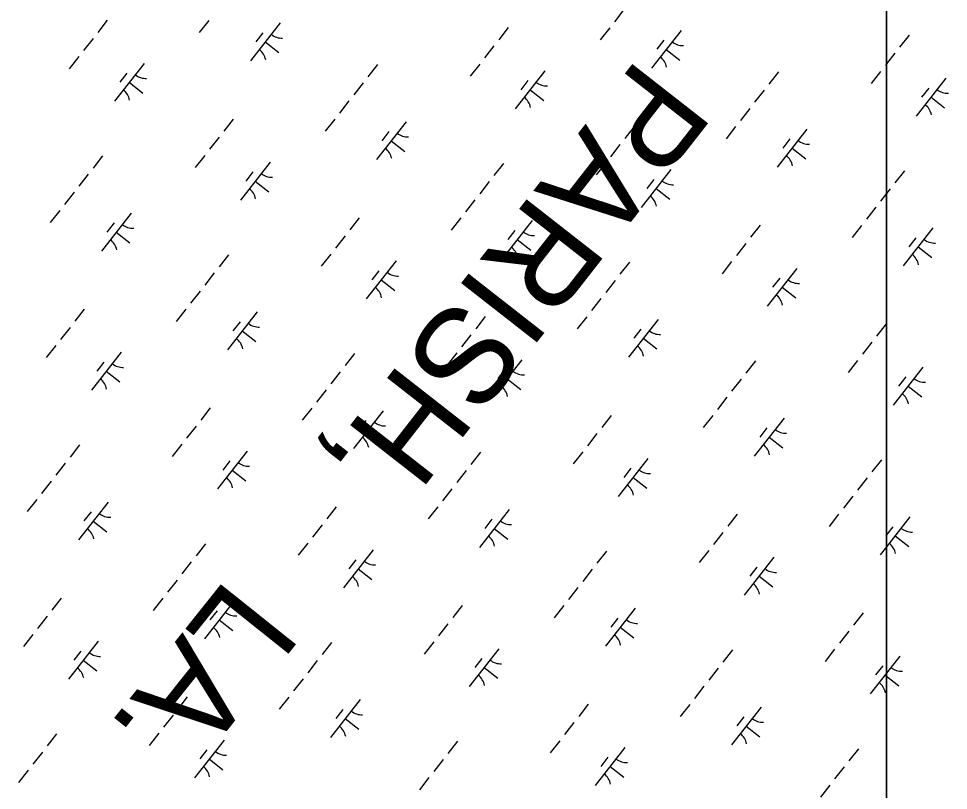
# Model space of a CAD drawing. Extents: x 3896831 to 3918110, y 171006 to 193349.
# Drawn here: x 3905077 to 3906044, y 182282 to 183084 of the extents above; entities that cross this region are included whole.
import ezdxf

# ---------------------------------------------------------------- set-up
doc = ezdxf.new("R2010")
doc.units = 0
doc.layers.add('V-TOPO-GNAM-IDEN', color=7, linetype='Continuous')
doc.layers.add('V-WETL-SWMP', color=7, linetype='Continuous')

msp = doc.modelspace()

# ---------------------------------------------------------------- linework, layer by layer
at = {"layer": 'V-WETL-SWMP'}
for p, q in [((3905979.34, 184854.89), (3905979.34, 179465.22)), ((3905979.34, 179465.22), (3905979.34, 184854.89)), ((3905706.44, 183092.9), (3905696.57, 183080.31)), ((3905169.53, 183081.84), (3905159.66, 183069.25)), ((3905275, 183081.71), (3905265.13, 183069.12)), ((3905349.13, 183078.97), (3905318.29, 183039.62)), ((3905331.34, 183068.78), (3905323.94, 183059.33)), ((3905586.18, 183074.14), (3905576.31, 183061.55)), ((3905691.64, 183074.01), (3905681.77, 183061.42)), ((3905765.77, 183071.27), (3905734.93, 183031.92)), ((3906002.82, 183066.44), (3905992.95, 183053.85)), ((3905154.73, 183062.95), (3905144.86, 183050.36)), ((3905333.71, 183059.3), (3905347.88, 183048.19)), ((3905747.98, 183061.08), (3905740.58, 183051.63)), ((3905571.37, 183055.25), (3905561.5, 183042.66)), ((3905750.35, 183051.6), (3905764.52, 183040.49)), ((3905988.01, 183047.55), (3905979.34, 183036.48)), ((3905139.92, 183044.06), (3905130.05, 183031.47)), ((3905207.74, 183037.02), (3905176.9, 182997.67)), ((3905450.33, 183035.77), (3905440.46, 183023.18)), ((3905556.57, 183036.36), (3905546.7, 183023.77)), ((3905624.38, 183029.32), (3905593.54, 182989.97)), ((3905866.97, 183028.07), (3905857.1, 183015.48)), ((3905973.21, 183028.66), (3905963.34, 183016.07)), ((3905979.34, 183036.48), (3905978.14, 183034.96)), ((3905189.95, 183026.83), (3905182.54, 183017.39)), ((3905606.59, 183019.13), (3905599.19, 183009.69)), ((3906041.03, 183021.62), (3906010.18, 182982.27)), ((3905192.32, 183017.35), (3905206.49, 183006.24)), ((3905435.53, 183016.88), (3905425.66, 183004.29)), ((3905608.96, 183009.65), (3905623.13, 182998.54)), ((3905852.17, 183009.18), (3905842.3, 182996.59)), ((3906023.23, 183011.43), (3906015.83, 183001.99)), ((3906025.6, 183001.95), (3906039.77, 182990.84)), ((3905420.72, 182997.99), (3905410.85, 182985.4)), ((3905837.36, 182990.29), (3905827.49, 182977.7)), ((3905300.45, 182979.23), (3905290.58, 182966.64)), ((3905405.92, 182979.1), (3905396.05, 182966.51)), ((3905480.05, 182976.37), (3905449.21, 182937.01)), ((3905717.1, 182971.53), (3905707.23, 182958.94)), ((3905822.56, 182971.4), (3905812.69, 182958.81)), ((3905285.65, 182960.34), (3905275.78, 182947.75)), ((3905462.26, 182966.17), (3905454.85, 182956.73)), ((3905896.69, 182968.67), (3905865.85, 182929.31)), ((3905464.63, 182956.69), (3905478.79, 182945.58)), ((3905702.29, 182952.64), (3905692.42, 182940.05)), ((3905878.9, 182958.47), (3905871.5, 182949.03)), ((3905164.61, 182940.86), (3905154.74, 182928.27)), ((3905270.84, 182941.45), (3905260.97, 182928.86)), ((3905881.27, 182948.99), (3905895.44, 182937.88)), ((3905338.66, 182934.42), (3905307.82, 182895.06)), ((3905581.25, 182933.16), (3905571.38, 182920.57)), ((3905687.49, 182933.75), (3905677.62, 182921.16)), ((3905149.8, 182921.97), (3905139.93, 182909.38)), ((3905320.87, 182924.22), (3905313.46, 182914.78)), ((3905755.3, 182926.72), (3905724.46, 182887.36)), ((3905997.89, 182925.46), (3905988.02, 182912.87)), ((3905323.24, 182914.74), (3905337.4, 182903.64)), ((3905566.44, 182914.27), (3905556.57, 182901.68)), ((3905737.51, 182916.52), (3905730.11, 182907.08)), ((3905135, 182903.08), (3905125.13, 182890.49)), ((3905739.88, 182907.04), (3905754.05, 182895.94)), ((3905983.09, 182906.57), (3905979.34, 182901.79)), ((3905551.64, 182895.38), (3905541.77, 182882.79)), ((3905979.34, 182901.79), (3905973.22, 182893.98)), ((3905120.19, 182884.19), (3905110.32, 182871.6)), ((3905968.28, 182887.68), (3905958.41, 182875.09)), ((3905194.32, 182881.46), (3905163.48, 182842.1)), ((3905431.37, 182876.62), (3905421.5, 182864.03)), ((3905536.83, 182876.49), (3905526.96, 182863.9)), ((3905610.97, 182873.76), (3905580.12, 182834.4)), ((3905176.53, 182871.26), (3905169.13, 182861.82)), ((3905593.17, 182863.56), (3905585.77, 182854.12)), ((3905848.01, 182868.92), (3905838.14, 182856.33)), ((3905953.48, 182868.79), (3905943.61, 182856.2)), ((3906027.61, 182866.06), (3905996.77, 182826.7)), ((3905178.9, 182861.78), (3905193.07, 182850.68)), ((3905416.57, 182857.73), (3905406.7, 182845.14)), ((3905595.55, 182854.08), (3905609.71, 182842.98)), ((3906009.82, 182855.86), (3906002.41, 182846.42)), ((3905833.21, 182850.03), (3905823.34, 182837.44)), ((3906012.19, 182846.38), (3906026.36, 182835.28)), ((3905295.52, 182838.25), (3905285.65, 182825.66)), ((3905401.76, 182838.84), (3905391.89, 182826.25)), ((3905469.58, 182831.81), (3905438.73, 182792.45)), ((3905712.17, 182830.55), (3905702.3, 182817.96)), ((3905818.4, 182831.14), (3905808.53, 182818.55)), ((3905280.72, 182819.36), (3905270.85, 182806.77)), ((3905451.78, 182821.61), (3905444.38, 182812.17)), ((3905886.22, 182824.11), (3905855.38, 182784.75)), ((3905454.16, 182812.13), (3905468.32, 182801.03)), ((3905697.36, 182811.66), (3905687.49, 182799.07)), ((3905868.43, 182813.91), (3905861.02, 182804.47)), ((3905265.91, 182800.47), (3905256.04, 182787.88)), ((3905870.8, 182804.43), (3905884.97, 182793.33)), ((3905682.56, 182792.77), (3905672.69, 182780.18)), ((3905145.65, 182781.71), (3905135.78, 182769.12)), ((3905251.11, 182781.58), (3905241.24, 182768.99)), ((3905325.24, 182778.85), (3905294.4, 182739.49)), ((3905307.45, 182768.65), (3905300.05, 182759.21)), ((3905562.29, 182774.01), (3905552.42, 182761.42)), ((3905667.75, 182773.88), (3905657.88, 182761.29)), ((3905741.89, 182771.15), (3905711.04, 182731.79)), ((3905130.84, 182762.82), (3905120.97, 182750.23)), ((3905309.82, 182759.17), (3905323.99, 182748.07)), ((3905724.09, 182760.95), (3905716.69, 182751.51)), ((3905978.93, 182766.31), (3905969.06, 182753.72)), ((3905547.48, 182755.12), (3905537.61, 182742.53)), ((3905726.46, 182751.47), (3905740.63, 182740.37)), ((3905116.04, 182743.93), (3905106.17, 182731.34)), ((3905964.13, 182747.42), (3905954.26, 182734.83)), ((3905183.85, 182736.9), (3905153.01, 182697.55)), ((3905426.44, 182735.64), (3905416.57, 182723.05)), ((3905532.68, 182736.23), (3905522.81, 182723.64)), ((3905600.5, 182729.2), (3905569.65, 182689.85)), ((3905949.32, 182728.54), (3905939.45, 182715.94)), ((3905166.06, 182726.7), (3905158.66, 182717.26)), ((3905582.7, 182719), (3905575.3, 182709.56)), ((3905843.09, 182727.94), (3905833.22, 182715.35)), ((3906017.14, 182721.5), (3905986.3, 182682.15)), ((3905168.43, 182717.22), (3905182.6, 182706.12)), ((3905411.64, 182716.75), (3905401.77, 182704.16)), ((3905585.07, 182709.52), (3905599.24, 182698.42)), ((3905828.28, 182709.05), (3905818.41, 182696.46)), ((3905999.35, 182711.3), (3905991.94, 182701.86)), ((3906001.72, 182701.82), (3906015.88, 182690.72)), ((3905396.83, 182697.86), (3905386.96, 182685.27)), ((3905813.48, 182690.16), (3905803.61, 182677.57)), ((3905276.56, 182679.11), (3905266.69, 182666.51)), ((3905382.03, 182678.97), (3905372.16, 182666.38)), ((3905456.16, 182676.24), (3905425.32, 182636.89)), ((3905693.21, 182671.41), (3905683.34, 182658.81)), ((3905798.67, 182671.27), (3905788.8, 182658.68)), ((3905438.37, 182666.04), (3905430.97, 182656.6)), ((3905872.8, 182668.54), (3905841.96, 182629.19)), ((3905261.76, 182660.22), (3905251.89, 182647.62)), ((3905440.74, 182656.56), (3905454.91, 182645.46)), ((3905678.4, 182652.52), (3905668.53, 182639.92)), ((3905855.01, 182658.34), (3905847.61, 182648.9)), ((3905246.96, 182641.33), (3905237.09, 182628.73)), ((3905857.38, 182648.86), (3905871.55, 182637.76)), ((3905140.72, 182640.73), (3905130.85, 182628.14)), ((3905314.77, 182634.29), (3905283.93, 182594.94)), ((3905557.36, 182633.03), (3905547.49, 182620.44)), ((3905663.6, 182633.63), (3905653.73, 182621.03)), ((3905125.91, 182621.85), (3905116.04, 182609.25)), ((3905296.98, 182624.1), (3905289.58, 182614.65)), ((3905731.41, 182626.59), (3905700.57, 182587.24)), ((3905974, 182625.33), (3905964.13, 182612.74)), ((3905299.35, 182614.61), (3905313.52, 182603.51)), ((3905542.56, 182614.15), (3905532.69, 182601.55)), ((3905713.62, 182616.4), (3905706.22, 182606.95)), ((3905111.11, 182602.96), (3905101.24, 182590.36)), ((3905715.99, 182606.91), (3905730.16, 182595.81)), ((3905959.2, 182606.45), (3905949.33, 182593.85)), ((3905527.75, 182595.26), (3905517.88, 182582.66)), ((3905096.3, 182584.07), (3905086.43, 182571.47)), ((3905944.39, 182587.56), (3905934.52, 182574.96)), ((3905170.44, 182581.33), (3905139.59, 182541.98)), ((3905407.48, 182576.5), (3905397.61, 182563.9)), ((3905512.95, 182576.37), (3905503.08, 182563.77)), ((3905587.08, 182573.63), (3905556.24, 182534.28)), ((3905152.64, 182571.14), (3905145.24, 182561.69)), ((3905824.13, 182568.8), (3905814.26, 182556.2)), ((3905929.59, 182568.67), (3905919.72, 182556.07)), ((3906003.72, 182565.93), (3905979.34, 182534.82)), ((3905155.02, 182561.65), (3905169.18, 182550.55)), ((3905392.68, 182557.61), (3905382.81, 182545.01)), ((3905569.29, 182563.44), (3905561.88, 182553.99)), ((3905985.93, 182555.74), (3905979.34, 182547.33)), ((3905571.66, 182553.95), (3905585.83, 182542.85)), ((3905809.32, 182549.91), (3905799.45, 182537.31)), ((3905979.34, 182547.33), (3905978.53, 182546.29)), ((3905988.3, 182546.25), (3906002.47, 182535.15)), ((3905271.64, 182538.13), (3905261.77, 182525.53)), ((3905377.87, 182538.72), (3905368, 182526.12)), ((3905445.69, 182531.68), (3905414.85, 182492.33)), ((3905688.28, 182530.43), (3905678.41, 182517.83)), ((3905794.52, 182531.02), (3905784.65, 182518.42)), ((3905979.34, 182534.82), (3905972.88, 182526.58)), ((3905256.83, 182519.24), (3905246.96, 182506.64)), ((3905427.9, 182521.49), (3905420.49, 182512.04)), ((3905862.33, 182523.98), (3905831.49, 182484.63)), ((3905430.27, 182512.01), (3905444.44, 182500.9)), ((3905673.47, 182511.54), (3905663.6, 182498.94)), ((3905844.54, 182513.79), (3905837.14, 182504.34)), ((3905242.03, 182500.35), (3905232.16, 182487.75)), ((3905846.91, 182504.31), (3905861.08, 182493.2)), ((3905658.67, 182492.65), (3905648.8, 182480.05)), ((3905121.76, 182481.59), (3905111.89, 182469)), ((3905227.22, 182481.46), (3905217.35, 182468.86)), ((3905301.36, 182478.72), (3905270.51, 182439.37)), ((3905283.56, 182468.53), (3905276.16, 182459.08)), ((3905538.4, 182473.89), (3905528.53, 182461.3)), ((3905643.86, 182473.76), (3905633.99, 182461.16)), ((3905718, 182471.02), (3905687.16, 182431.67)), ((3905106.95, 182462.7), (3905097.08, 182450.11)), ((3905285.93, 182459.05), (3905300.1, 182447.94)), ((3905700.21, 182460.83), (3905692.8, 182451.38)), ((3905955.04, 182466.19), (3905945.17, 182453.6)), ((3905523.6, 182455), (3905513.73, 182442.41)), ((3905702.58, 182451.35), (3905716.74, 182440.24)), ((3905092.15, 182443.81), (3905082.28, 182431.22)), ((3905940.24, 182447.3), (3905930.37, 182434.71)), ((3905159.97, 182436.77), (3905129.12, 182397.42)), ((3905402.56, 182435.52), (3905392.69, 182422.92)), ((3905508.79, 182436.11), (3905498.92, 182423.52)), ((3905576.61, 182429.07), (3905545.76, 182389.72)), ((3905142.17, 182426.58), (3905134.77, 182417.13)), ((3905819.2, 182427.82), (3905809.33, 182415.22)), ((3905925.43, 182428.41), (3905915.57, 182415.82)), ((3905993.25, 182421.37), (3905979.34, 182403.62)), ((3905144.54, 182417.1), (3905158.71, 182405.99)), ((3905387.75, 182416.63), (3905377.88, 182404.03)), ((3905558.82, 182418.88), (3905551.41, 182409.43)), ((3905561.19, 182409.4), (3905575.35, 182398.29)), ((3905975.46, 182411.18), (3905968.06, 182401.73)), ((3905804.39, 182408.93), (3905794.52, 182396.34)), ((3905979.34, 182403.62), (3905962.41, 182382.02)), ((3905977.83, 182401.7), (3905979.34, 182400.51)), ((3905979.34, 182400.51), (3905992, 182390.59)), ((3905372.95, 182397.74), (3905363.08, 182385.15)), ((3905789.59, 182390.04), (3905779.72, 182377.45)), ((3905252.68, 182378.98), (3905242.81, 182366.39)), ((3905358.14, 182378.85), (3905348.27, 182366.26)), ((3905432.27, 182376.11), (3905401.43, 182336.76)), ((3905669.32, 182371.28), (3905659.45, 182358.69)), ((3905774.78, 182371.15), (3905764.91, 182358.56)), ((3905414.48, 182365.92), (3905407.08, 182356.47)), ((3905848.92, 182368.41), (3905818.07, 182329.06)), ((3905237.87, 182360.09), (3905228, 182347.5)), ((3905416.85, 182356.44), (3905431.02, 182345.33)), ((3905654.52, 182352.39), (3905644.65, 182339.8)), ((3905831.12, 182358.22), (3905823.72, 182348.77)), ((3905833.5, 182348.74), (3905847.66, 182337.63)), ((3905116.83, 182340.61), (3905106.96, 182328.02)), ((3905223.07, 182341.2), (3905213.2, 182328.61)), ((3905290.88, 182334.16), (3905260.04, 182294.81)), ((3905533.47, 182332.91), (3905523.6, 182320.32)), ((3905639.71, 182333.5), (3905629.84, 182320.91)), ((3905273.09, 182323.97), (3905265.69, 182314.53)), ((3905707.53, 182326.46), (3905676.68, 182287.11)), ((3905950.12, 182325.21), (3905940.25, 182312.62)), ((3905102.03, 182321.72), (3905092.16, 182309.13)), ((3905275.46, 182314.49), (3905289.63, 182303.38)), ((3905518.67, 182314.02), (3905508.8, 182301.43)), ((3905689.73, 182316.27), (3905682.33, 182306.83)), ((3905692.11, 182306.79), (3905706.27, 182295.68)), ((3905935.31, 182306.32), (3905925.44, 182293.73)), ((3905087.22, 182302.83), (3905077.35, 182290.24)), ((3905503.86, 182295.13), (3905493.99, 182282.54)), ((3905920.51, 182287.43), (3905910.64, 182274.84))]:
    msp.add_line(p, q, dxfattribs=at)
for centre, start, end in [((3905350.93, 183080.89), 231.14028, 272.68394), ((3905767.58, 183073.19), 231.14028, 272.68394), ((3905316.86, 183037.41), 11.14028, 52.68394), ((3905733.5, 183029.71), 11.14028, 52.68394), ((3905209.54, 183038.94), 231.14028, 272.68394), ((3905175.47, 182995.46), 11.14028, 52.68394), ((3905626.19, 183031.24), 231.14028, 272.68394), ((3906042.83, 183023.54), 231.14028, 272.68394), ((3905592.11, 182987.76), 11.14028, 52.68394), ((3906008.75, 182980.06), 11.14028, 52.68394), ((3905481.85, 182978.28), 231.14028, 272.68394), ((3905898.5, 182970.58), 231.14028, 272.68394), ((3905447.78, 182934.8), 11.14028, 52.68394), ((3905864.42, 182927.1), 11.14028, 52.68394), ((3905340.46, 182936.33), 231.14028, 272.68394), ((3905757.11, 182928.63), 231.14028, 272.68394), ((3905306.39, 182892.85), 11.14028, 52.68394), ((3905723.03, 182885.15), 11.14028, 52.68394), ((3905196.13, 182883.37), 231.14028, 272.68394), ((3905162.05, 182839.89), 11.14028, 52.68394), ((3905612.77, 182875.67), 231.14028, 272.68394), ((3906029.41, 182867.97), 231.14028, 272.68394), ((3905578.69, 182832.19), 11.14028, 52.68394), ((3905995.34, 182824.49), 11.14028, 52.68394), ((3905471.38, 182833.72), 231.14028, 272.68394), ((3905888.02, 182826.02), 231.14028, 272.68394), ((3905437.3, 182790.24), 11.14028, 52.68394), ((3905853.95, 182782.54), 11.14028, 52.68394), ((3905327.05, 182780.76), 231.14028, 272.68394), ((3905743.69, 182773.06), 231.14028, 272.68394), ((3905292.97, 182737.28), 11.14028, 52.68394), ((3905709.61, 182729.58), 11.14028, 52.68394), ((3905185.66, 182738.82), 231.14028, 272.68394), ((3905151.58, 182695.34), 11.14028, 52.68394), ((3905602.3, 182731.12), 231.14028, 272.68394), ((3906018.94, 182723.42), 231.14028, 272.68394), ((3905568.22, 182687.64), 11.14028, 52.68394), ((3905984.86, 182679.94), 11.14028, 52.68394), ((3905457.97, 182678.16), 231.14028, 272.68394), ((3905874.61, 182670.46), 231.14028, 272.68394), ((3905423.89, 182634.68), 11.14028, 52.68394), ((3905840.53, 182626.98), 11.14028, 52.68394), ((3905316.58, 182636.21), 231.14028, 272.68394), ((3905733.22, 182628.51), 231.14028, 272.68394), ((3905282.5, 182592.73), 11.14028, 52.68394), ((3905699.14, 182585.03), 11.14028, 52.68394), ((3905172.24, 182583.25), 231.14028, 272.68394), ((3905588.88, 182575.55), 231.14028, 272.68394), ((3905138.16, 182539.77), 11.14028, 52.68394), ((3905554.81, 182532.07), 11.14028, 52.68394), ((3906005.53, 182567.85), 231.14028, 272.68394), ((3905971.45, 182524.37), 11.14028, 52.68394), ((3905447.49, 182533.6), 231.14028, 272.68394), ((3905864.14, 182525.9), 231.14028, 272.68394), ((3905413.42, 182490.12), 11.14028, 52.68394), ((3905830.06, 182482.42), 11.14028, 52.68394), ((3905303.16, 182480.64), 231.14028, 272.68394), ((3905719.8, 182472.94), 231.14028, 272.68394), ((3905269.08, 182437.16), 11.14028, 52.68394), ((3905685.72, 182429.46), 11.14028, 52.68394), ((3905161.77, 182438.69), 231.14028, 272.68394), ((3905127.69, 182395.21), 11.14028, 52.68394), ((3905578.41, 182430.99), 231.14028, 272.68394), ((3905995.06, 182423.29), 231.14028, 272.68394), ((3905544.33, 182387.51), 11.14028, 52.68394), ((3905960.98, 182379.81), 11.14028, 52.68394), ((3905434.08, 182378.03), 231.14028, 272.68394), ((3905850.72, 182370.33), 231.14028, 272.68394), ((3905400, 182334.55), 11.14028, 52.68394), ((3905816.64, 182326.85), 11.14028, 52.68394), ((3905292.69, 182336.08), 231.14028, 272.68394), ((3905709.33, 182328.38), 231.14028, 272.68394), ((3905258.61, 182292.6), 11.14028, 52.68394), ((3905675.25, 182284.9), 11.14028, 52.68394)]:
    msp.add_arc(centre, 17.62, start, end, dxfattribs=at)

# ---------------------------------------------------------------- texts
at = {"layer": 'V-TOPO-GNAM-IDEN'}
for s, rotation, p in [('PARISH,', 231.99519, (3905721.86, 183045)), ('LA.', 231.39519, (3905294.33, 182504.53))]:
    msp.add_text(s, height=100, rotation=rotation, dxfattribs=at).set_placement(p)

doc.saveas('drawing.dxf')
